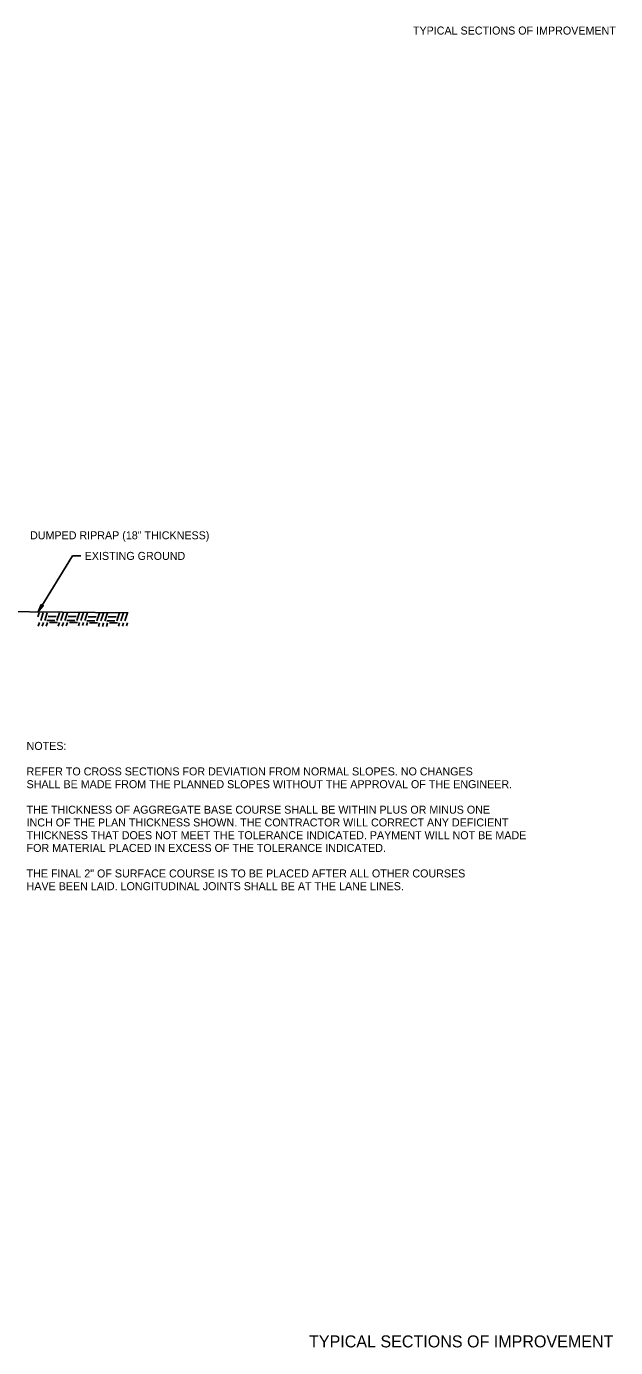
# Model space of a CAD drawing. Extents: x 1461570 to 1461697, y 1686711 to 1686957.
# Drawn here: x 1461652.8 to 1461697, y 1686857.5 to 1686956.5 of the extents above; entities that cross this region are included whole.
import ezdxf

# ---------------------------------------------------------------- set-up
doc = ezdxf.new("R2010")
doc.units = 0
for name, color, linetype in [('1', 7, 'Continuous'), ('19', 7, 'Continuous'), ('42', 7, 'Continuous'), ('G-ANNO-TEXT', 7, 'Continuous'), ('R_Draft', 7, 'Continuous')]:
    doc.layers.add(name, color=color, linetype=linetype)

msp = doc.modelspace()

# ---------------------------------------------------------------- linework, layer by layer
at = {"layer": '19'}
for p, q in [((1461653.696, 1686912.611), (1461653.919, 1686913.178)), ((1461653.919, 1686913.178), (1461654.097, 1686913.068)), ((1461646.812, 1686912.672), (1461660.437, 1686912.552)), ((1461654.097, 1686913.068), (1461653.696, 1686912.611)), ((1461653.769, 1686912.752), (1461653.962, 1686913.146)), ((1461654.056, 1686913.09), (1461653.792, 1686912.741))]:
    msp.add_line(p, q, dxfattribs=at)
msp.add_lwpolyline([(1461656.878, 1686916.81), (1461656.278, 1686916.81), (1461653.696, 1686912.611)], dxfattribs=at)
at = {"layer": '42'}
for p, q in [((1461653.677, 1686912.241), (1461653.779, 1686912.547)), ((1461653.89, 1686911.98), (1461654.078, 1686912.545)), ((1461654.19, 1686911.98), (1461654.377, 1686912.543)), ((1461654.44, 1686912.28), (1461655.04, 1686912.28)), ((1461655.09, 1686911.98), (1461655.28, 1686912.552)), ((1461655.39, 1686911.98), (1461655.583, 1686912.559)), ((1461655.69, 1686911.98), (1461655.885, 1686912.565)), ((1461655.94, 1686912.28), (1461656.54, 1686912.28)), ((1461656.59, 1686911.98), (1461656.79, 1686912.58)), ((1461656.637, 1686912.58), (1461656.64, 1686912.58)), ((1461656.89, 1686911.98), (1461657.09, 1686912.58)), ((1461657.19, 1686911.98), (1461657.39, 1686912.58)), ((1461657.445, 1686912.25), (1461658.045, 1686912.25)), ((1461658.095, 1686911.95), (1461658.286, 1686912.522)), ((1461658.395, 1686911.95), (1461658.588, 1686912.528)), ((1461658.695, 1686911.95), (1461658.89, 1686912.534)), ((1461658.945, 1686912.25), (1461659.545, 1686912.25)), ((1461659.595, 1686911.95), (1461659.795, 1686912.55)), ((1461659.642, 1686912.55), (1461659.645, 1686912.55)), ((1461659.895, 1686911.95), (1461660.095, 1686912.55)), ((1461660.195, 1686911.95), (1461660.395, 1686912.55)), ((1461653.696, 1686911.548), (1461653.79, 1686911.83)), ((1461653.995, 1686911.546), (1461654.09, 1686911.83)), ((1461654.294, 1686911.543), (1461654.39, 1686911.83)), ((1461654.34, 1686911.98), (1461654.94, 1686911.98)), ((1461654.54, 1686911.83), (1461655.14, 1686911.83)), ((1461655.197, 1686911.551), (1461655.29, 1686911.83)), ((1461655.499, 1686911.557), (1461655.59, 1686911.83)), ((1461655.801, 1686911.563), (1461655.89, 1686911.83)), ((1461655.84, 1686911.98), (1461656.44, 1686911.98)), ((1461656.04, 1686911.83), (1461656.59, 1686911.83)), ((1461656.59, 1686911.83), (1461656.64, 1686911.83)), ((1461656.707, 1686911.582), (1461656.79, 1686911.83)), ((1461657.009, 1686911.588), (1461657.09, 1686911.83)), ((1461657.311, 1686911.594), (1461657.39, 1686911.83)), ((1461657.345, 1686911.95), (1461657.945, 1686911.95)), ((1461657.545, 1686911.8), (1461658.145, 1686911.8)), ((1461658.202, 1686911.52), (1461658.295, 1686911.8)), ((1461658.504, 1686911.526), (1461658.595, 1686911.8)), ((1461658.806, 1686911.532), (1461658.895, 1686911.8)), ((1461658.845, 1686911.95), (1461659.445, 1686911.95)), ((1461659.045, 1686911.8), (1461659.595, 1686911.8)), ((1461659.595, 1686911.8), (1461659.645, 1686911.8)), ((1461659.712, 1686911.551), (1461659.795, 1686911.8)), ((1461660.014, 1686911.557), (1461660.095, 1686911.8)), ((1461660.317, 1686911.563), (1461660.395, 1686911.8))]:
    msp.add_line(p, q, dxfattribs=at)

# ---------------------------------------------------------------- texts
at = {"layer": '1'}
for s, p in [('NOTES:', (1461652.825, 1686902.27)), ('REFER TO CROSS SECTIONS FOR DEVIATION FROM NORMAL SLOPES. NO CHANGES', (1461652.825, 1686900.358)), ('SHALL BE MADE FROM THE PLANNED SLOPES WITHOUT THE APPROVAL OF THE ENGINEER.', (1461652.825, 1686899.402)), ('THE THICKNESS OF AGGREGATE BASE COURSE SHALL BE WITHIN PLUS OR MINUS ONE', (1461652.825, 1686897.49)), ('INCH OF THE PLAN THICKNESS SHOWN. THE CONTRACTOR WILL CORRECT ANY DEFICIENT', (1461652.825, 1686896.534)), ('THICKNESS THAT DOES NOT MEET THE TOLERANCE INDICATED. PAYMENT WILL NOT BE MADE', (1461652.825, 1686895.578)), ('FOR MATERIAL PLACED IN EXCESS OF THE TOLERANCE INDICATED.', (1461652.825, 1686894.622)), ('THE FINAL 2" OF SURFACE COURSE IS TO BE PLACED AFTER ALL OTHER COURSES', (1461652.825, 1686892.711)), ('HAVE BEEN LAID. LONGITUDINAL JOINTS SHALL BE AT THE LANE LINES.', (1461652.825, 1686891.755))]:
    msp.add_text(s, height=0.6, dxfattribs=at).set_placement(p)
at = {"layer": 'G-ANNO-TEXT'}
for height, p in [(0.6, (1461681.775, 1686955.891)), (0.9, (1461673.991, 1686857.484))]:
    msp.add_text('TYPICAL SECTIONS OF IMPROVEMENT', height=height, dxfattribs=at).set_placement(p)
at = {"layer": 'R_Draft'}
for s, p in [('DUMPED RIPRAP (18" THICKNESS)', (1461653.085, 1686918.057)), ('EXISTING GROUND', (1461657.178, 1686916.511))]:
    msp.add_text(s, height=0.6, dxfattribs=at).set_placement(p)

doc.saveas('drawing.dxf')
